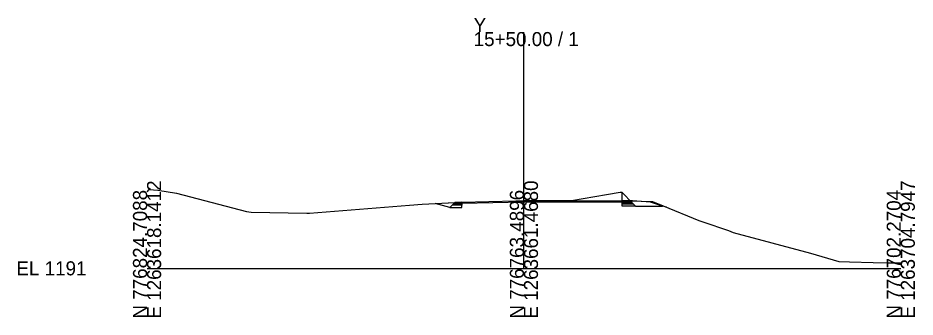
# Model space of a CAD drawing. Extents: x -51 to 1263719, y -10 to 776845.
# Drawn here: x 1124.3 to 1302.8, y 490.3 to 549.8 of the extents above; entities that cross this region are included whole.
import ezdxf

# ---------------------------------------------------------------- set-up
doc = ezdxf.new("R2010")
doc.units = 0
for name, color, linetype in [('Exist Cross Section Cell', 7, 'Continuous'), ('Exist XS Ground Line', 7, 'Continuous'), ('Prop XS Earthwork Shape', 7, 'Continuous')]:
    doc.layers.add(name, color=color, linetype=linetype)

msp = doc.modelspace()

# ---------------------------------------------------------------- linework, layer by layer
at = {"layer": 'Exist Cross Section Cell'}
for p, q in [((1225, 500), (1225, 547.02)), ((1150, 500), (1225, 500)), ((1225, 500), (1300, 500))]:
    msp.add_line(p, q, dxfattribs=at)
at = {"layer": 'Exist XS Ground Line'}
msp.add_lwpolyline([(1150, 515.25), (1150.43, 515.67), (1152.14, 515.58), (1155.88, 514.96), (1169.76, 511.34), (1170.75, 511.21), (1181.79, 510.96), (1182.36, 510.97), (1202.22, 512.6), (1204.72, 512.8), (1212.64, 513.17), (1223.36, 513.4), (1224.34, 513.42), (1225, 513.42), (1225.65, 513.43), (1228.66, 513.46), (1229.01, 513.46), (1232.77, 513.44), (1234.49, 513.46), (1246.18, 513.43), (1248.31, 513.36), (1250.6, 513.33), (1252.69, 512.41), (1259.83, 509.53), (1260.63, 509.27), (1265.71, 507.52), (1266.61, 507.13), (1282.04, 503.03), (1287.69, 501.36), (1289.8, 501.3), (1294.47, 501.16), (1297.22, 501.12), (1300, 501.11)], dxfattribs=at)
at = {"layer": 'Prop XS Earthwork Shape'}
for points in [[(1225, 513.42), (1244.53, 513.44), (1244.53, 515.1), (1244.15, 515.06), (1241.42, 514.61), (1234.49, 513.46), (1232.77, 513.44), (1229.01, 513.46), (1228.66, 513.46), (1225.65, 513.43)], [(1244.53, 513.44), (1244.53, 515.1), (1245.02, 514.64), (1246.17, 513.44)], [(1210.26, 512.08), (1207.31, 512.92), (1211.28, 513.1), (1211.07, 512.88), (1210.72, 512.54)], [(1212.64, 512.58), (1210.72, 512.54), (1210.26, 512.08), (1212.64, 512.12)], [(1212.64, 512.58), (1210.72, 512.54), (1211.07, 512.88), (1212.64, 512.92)], [(1212.64, 512.92), (1212.64, 513.17), (1211.28, 513.1), (1211.07, 512.88)], [(1225, 513.42), (1244.53, 513.44), (1244.53, 513.19), (1225, 513.17), (1212.64, 512.92), (1212.64, 513.17), (1223.36, 513.4), (1224.34, 513.42)], [(1244.53, 513.19), (1246.42, 513.19), (1246.18, 513.43), (1246.17, 513.44), (1244.53, 513.44)], [(1244.53, 513.19), (1246.42, 513.19), (1246.75, 512.86), (1244.53, 512.86)], [(1246.75, 512.86), (1247.21, 512.4), (1244.53, 512.4), (1244.53, 512.86)], [(1246.75, 512.86), (1247.21, 512.4), (1252.58, 512.4), (1250.18, 513.2), (1246.6, 513.41), (1246.18, 513.43), (1246.42, 513.19)], [(1248.31, 513.36), (1250.6, 513.33), (1252.69, 512.41), (1253.36, 512.14), (1252.58, 512.4), (1250.18, 513.2), (1246.6, 513.41)]]:
    msp.add_lwpolyline(points, close=True, dxfattribs=at)

# ---------------------------------------------------------------- texts
at = {"layer": 'Exist Cross Section Cell'}
for s, p in [('Y', (1215, 547.02)), ('15+50.00 / 1', (1215, 544.22)), ('EL 1191', (1124, 498.6))]:
    msp.add_text(s, height=2.8, dxfattribs=at).set_placement(p)
for s, p in [('E 1263618.1412', (1152.8, 490)), ('E 1263661.4680', (1227.8, 490)), ('E 1263704.7947', (1302.8, 490)), ('N 776824.7088', (1150, 490)), ('N 776763.4896', (1225, 490)), ('N 776702.2704', (1300, 490))]:
    msp.add_text(s, height=2.8, rotation=90, dxfattribs=at).set_placement(p)

doc.saveas('drawing.dxf')
